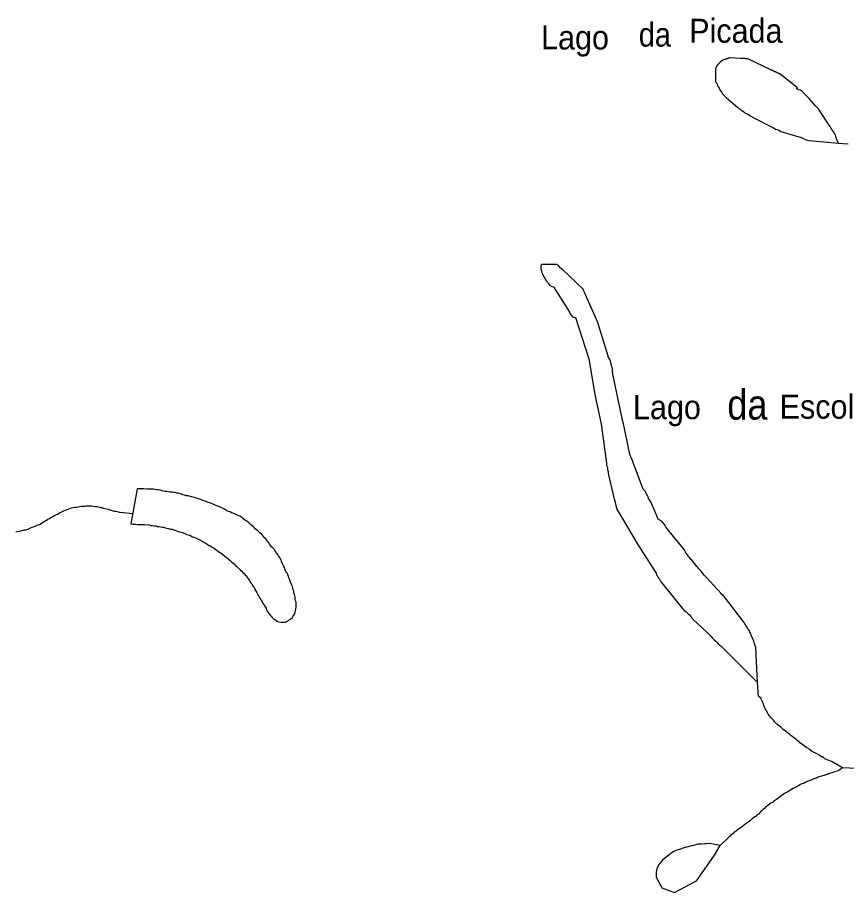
# Model space of a CAD drawing. Extents: x 785.9 to 812.4, y 7674.9 to 7703.1.
# Drawn here: x 788.66 to 791.421, y 7679.621 to 7682.535 of the extents above; entities that cross this region are included whole.
import ezdxf
from ezdxf.enums import TextEntityAlignment as Align

# ---------------------------------------------------------------- set-up
doc = ezdxf.new("R2010")
doc.units = 0
doc.header["$LTSCALE"] = 0.04
doc.linetypes.add('LONG_DASHED', pattern=[7.5, 6, -1.5])
for name, color, linetype, lineweight in [('2', 7, 'Continuous', 25), ('3', 7, 'LONG_DASHED', 25), ('7', 7, 'Continuous', 25)]:
    doc.layers.add(name, color=color, linetype=linetype, lineweight=lineweight)
doc.layers.add('61', color=7, linetype='Continuous')

msp = doc.modelspace()

# ---------------------------------------------------------------- linework, layer by layer
at = {"layer": '2'}
msp.add_line((789.058, 7680.9655), (789.0372, 7680.8488), dxfattribs=at)
for points in [[(789.5636, 7680.6691), (789.5619, 7680.6739), (789.5603, 7680.6796), (789.5579, 7680.6844), (789.5547, 7680.6885), (789.5522, 7680.6933), (789.5506, 7680.6982), (789.549, 7680.7039), (789.5458, 7680.7087), (789.5433, 7680.7136), (789.5417, 7680.7184), (789.5393, 7680.7233), (789.5377, 7680.7281), (789.5328, 7680.7379), (789.5296, 7680.7419), (789.5272, 7680.7468), (789.5239, 7680.7516), (789.5207, 7680.7557), (789.5174, 7680.7605), (789.5142, 7680.7646), (789.5102, 7680.7686), (789.5061, 7680.7726), (789.5029, 7680.7767), (789.4996, 7680.7815), (789.4964, 7680.7856), (789.4932, 7680.7896), (789.4899, 7680.7937), (789.4867, 7680.7985), (789.4827, 7680.8026), (789.4794, 7680.8066), (789.4754, 7680.8107), (789.4721, 7680.8147), (789.4681, 7680.818), (789.464, 7680.822), (789.46, 7680.826), (789.4519, 7680.8325), (789.4479, 7680.8366), (789.4446, 7680.8406), (789.4406, 7680.8438), (789.4357, 7680.8471), (789.4317, 7680.8511), (789.4276, 7680.8544), (789.4236, 7680.8576), (789.4187, 7680.86), (789.4147, 7680.8633), (789.4106, 7680.8665), (789.4066, 7680.8697), (789.4025, 7680.873), (789.3928, 7680.8778), (789.3872, 7680.8795), (789.3823, 7680.8819), (789.3775, 7680.8843), (789.3726, 7680.8859), (789.3678, 7680.8892), (789.3621, 7680.89), (789.3572, 7680.8924), (789.3475, 7680.8989), (789.3378, 7680.9037), (789.3233, 7680.9086), (789.3184, 7680.911), (789.3135, 7680.9134), (789.3087, 7680.9151), (789.3038, 7680.9175), (789.2893, 7680.9223), (789.2844, 7680.924), (789.2796, 7680.9256), (789.2747, 7680.928), (789.2698, 7680.9296), (789.265, 7680.9312), (789.2601, 7680.9329), (789.2545, 7680.9345), (789.2496, 7680.9361), (789.244, 7680.9377), (789.2391, 7680.9393), (789.2326, 7680.9409), (789.227, 7680.9426), (789.2213, 7680.9426), (789.2164, 7680.9442), (789.2108, 7680.9458), (789.2059, 7680.9474), (789.2011, 7680.949), (789.1962, 7680.9507), (789.1906, 7680.9515), (789.1849, 7680.9531), (789.1792, 7680.9531), (789.1736, 7680.9539), (789.1679, 7680.9539), (789.163, 7680.9555), (789.1574, 7680.9563), (789.1517, 7680.9571), (789.146, 7680.9579), (789.1363, 7680.9612), (789.1299, 7680.962), (789.1242, 7680.962), (789.1185, 7680.9636), (789.1129, 7680.9644), (789.0902, 7680.9644), (789.0805, 7680.9652), (789.0635, 7680.9652), (789.058, 7680.9655)], [(789.0372, 7680.8488), (789.0425, 7680.8479), (789.0538, 7680.8479), (789.0595, 7680.8471), (789.0708, 7680.8471), (789.0829, 7680.8463), (789.0983, 7680.8455), (789.104, 7680.8438), (789.1096, 7680.8438), (789.1145, 7680.8422), (789.1202, 7680.8422), (789.125, 7680.8406), (789.1307, 7680.8406), (789.1355, 7680.839), (789.1412, 7680.8382), (789.1469, 7680.8374), (789.1517, 7680.8358), (789.1574, 7680.8349), (789.163, 7680.8333), (789.1687, 7680.8317), (789.1744, 7680.8309), (789.1792, 7680.8293), (789.1849, 7680.8277), (789.1897, 7680.826), (789.1995, 7680.8228), (789.2043, 7680.8212)], [(789.2043, 7680.8212), (789.2092, 7680.8196), (789.214, 7680.818), (789.2189, 7680.8155), (789.2237, 7680.8139), (789.2286, 7680.8123), (789.2334, 7680.8107), (789.2431, 7680.8058), (789.248, 7680.8042), (789.2771, 7680.7896), (789.282, 7680.7864), (789.2868, 7680.7848), (789.2917, 7680.7815), (789.2965, 7680.7783), (789.3014, 7680.7759), (789.3063, 7680.7726), (789.3111, 7680.7702), (789.316, 7680.767), (789.3208, 7680.7637), (789.3249, 7680.7605), (789.3297, 7680.7573), (789.3338, 7680.754), (789.3386, 7680.7508), (789.3427, 7680.7476), (789.3508, 7680.7411), (789.3548, 7680.7379), (789.3589, 7680.7346), (789.3629, 7680.7314), (789.3669, 7680.7281), (789.3702, 7680.7241), (789.3742, 7680.7209), (789.3783, 7680.7176), (789.3823, 7680.7144), (789.3864, 7680.7103), (789.3904, 7680.7071), (789.4025, 7680.695), (789.4066, 7680.6909), (789.4106, 7680.6869), (789.4147, 7680.6836), (789.4179, 7680.6796), (789.422, 7680.6755), (789.4252, 7680.6707), (789.4284, 7680.6666), (789.4317, 7680.6618), (789.4341, 7680.6569), (789.4373, 7680.6529), (789.4406, 7680.6488), (789.443, 7680.644), (789.4454, 7680.6391), (789.4487, 7680.6351), (789.4503, 7680.6302), (789.4568, 7680.6205), (789.4592, 7680.6157), (789.4616, 7680.6108), (789.4649, 7680.606), (789.4673, 7680.6011), (789.4705, 7680.5971), (789.4729, 7680.5922), (789.4754, 7680.5873), (789.4786, 7680.5825), (789.481, 7680.5776), (789.4875, 7680.5679), (789.4891, 7680.5631), (789.4916, 7680.5582), (789.4948, 7680.5534), (789.5013, 7680.5453), (789.5045, 7680.5412), (789.5085, 7680.5372), (789.5126, 7680.5331), (789.5166, 7680.5299), (789.5215, 7680.5267), (789.5263, 7680.5242), (789.532, 7680.5226), (789.5377, 7680.5218), (789.5433, 7680.521), (789.5522, 7680.5218), (789.5619, 7680.5267), (789.566, 7680.5299), (789.57, 7680.5331), (789.5741, 7680.5364), (789.5773, 7680.5404), (789.5806, 7680.5445), (789.583, 7680.5493), (789.5854, 7680.5606), (789.587, 7680.5655), (789.5878, 7680.5712), (789.5878, 7680.5882), (789.5862, 7680.593), (789.5846, 7680.5987), (789.5846, 7680.6043), (789.5822, 7680.6141), (789.5806, 7680.6189), (789.5797, 7680.6246), (789.5781, 7680.6294), (789.5773, 7680.6351), (789.5757, 7680.6399), (789.5733, 7680.6448), (789.5708, 7680.6497), (789.5692, 7680.6545), (789.566, 7680.6642), (789.5636, 7680.6691)]]:
    msp.add_lwpolyline(points, dxfattribs=at)
at = {"layer": '3'}
for points in [[(791.0734, 7682.3987), (791.0718, 7682.3988), (791.0702, 7682.3989), (791.0686, 7682.399), (791.0686, 7682.399), (791.0332, 7682.4012), (791.0328, 7682.4011), (791.0312, 7682.4006), (791.0297, 7682.4001), (791.0282, 7682.3996), (791.0266, 7682.3991), (791.0251, 7682.3986), (791.0236, 7682.398), (791.022, 7682.3975), (791.0205, 7682.397), (791.019, 7682.3965), (791.0174, 7682.396), (791.0159, 7682.3955), (791.0144, 7682.395), (791.0095, 7682.3934), (791.0047, 7682.3901), (791.0006, 7682.3869), (790.9966, 7682.3828), (790.9925, 7682.3788), (790.9893, 7682.3747), (790.9868, 7682.3699), (790.9844, 7682.365), (790.9847, 7682.3222), (790.9849, 7682.3219), (790.9858, 7682.3205), (790.9867, 7682.3192), (790.9876, 7682.3178), (790.9885, 7682.3165), (790.9901, 7682.3141), (790.9917, 7682.3092), (790.9941, 7682.3044), (790.9966, 7682.2995), (790.999, 7682.2946), (791.0022, 7682.2898), (791.0055, 7682.2849), (791.0087, 7682.2809), (791.0127, 7682.2768), (791.02, 7682.2687), (791.0587, 7682.2353), (791.0591, 7682.235), (791.0604, 7682.2341), (791.0617, 7682.2332), (791.063, 7682.2322), (791.0644, 7682.2313), (791.0657, 7682.2304), (791.067, 7682.2295), (791.0683, 7682.2285), (791.0697, 7682.2276), (791.071, 7682.2267), (791.0791, 7682.221), (791.0831, 7682.2178), (791.088, 7682.2153), (791.0928, 7682.2129), (791.0977, 7682.2097), (791.1026, 7682.2064), (791.1123, 7682.2008), (791.1754, 7682.1684), (791.1754, 7682.1684), (791.1802, 7682.1668), (791.1851, 7682.1636), (791.1908, 7682.1619), (791.198, 7682.1587), (791.2029, 7682.1555), (791.2628, 7682.1377), (791.2676, 7682.1361), (791.2725, 7682.1344), (791.2773, 7682.132), (791.2822, 7682.1296), (791.287, 7682.128), (791.2927, 7682.1271), (791.2976, 7682.1255), (791.3089, 7682.1239), (791.3946, 7682.1167), (791.3939, 7682.1182), (791.3932, 7682.1196), (791.3924, 7682.1211), (791.3917, 7682.1225), (791.391, 7682.124), (791.3903, 7682.1254), (791.3895, 7682.1269), (791.3888, 7682.1283), (791.3881, 7682.1297), (791.3874, 7682.1312), (791.3866, 7682.1328), (791.3858, 7682.1393), (791.3841, 7682.1441), (791.3809, 7682.1482), (791.3785, 7682.153), (791.376, 7682.1579), (791.3728, 7682.1619), (791.3704, 7682.1668), (791.3671, 7682.1717), (791.3639, 7682.1765), (791.3607, 7682.1814), (791.355, 7682.1903), (791.3305, 7682.2281)], [(791.2582, 7682.3014), (791.2582, 7682.3014), (791.2004, 7682.3464), (791.199, 7682.3471), (791.1975, 7682.3478), (791.196, 7682.3485), (791.1946, 7682.3492), (791.1931, 7682.3499), (791.1916, 7682.3506), (791.1902, 7682.3513), (791.1887, 7682.352), (791.1873, 7682.3527), (791.1858, 7682.3534), (791.1843, 7682.3541), (791.1829, 7682.3547), (791.1814, 7682.3554), (791.1799, 7682.3561), (791.1785, 7682.3568), (791.177, 7682.3575), (791.1756, 7682.3582), (791.1741, 7682.3589), (791.1726, 7682.3596), (791.1712, 7682.3603), (791.1697, 7682.361), (791.1697, 7682.361), (791.0928, 7682.3975), (791.0912, 7682.3976), (791.0896, 7682.3977), (791.088, 7682.3978), (791.0863, 7682.3979), (791.0847, 7682.398), (791.0831, 7682.3981), (791.0815, 7682.3982), (791.0799, 7682.3983), (791.0783, 7682.3984), (791.0766, 7682.3985), (791.075, 7682.3986), (791.0734, 7682.3987)], [(791.3305, 7682.2281), (791.3303, 7682.2284), (791.3194, 7682.2404), (791.2959, 7682.2663), (791.2927, 7682.2704), (791.2887, 7682.2736), (791.2846, 7682.2777), (791.2806, 7682.2817), (791.2765, 7682.2857), (791.2725, 7682.2898), (791.2676, 7682.293), (791.2628, 7682.2946), (791.2547, 7682.2971), (791.2579, 7682.3011), (791.2582, 7682.3014)], [(790.8814, 7680.7619), (790.8291, 7680.826), (790.8226, 7680.8349), (790.8194, 7680.839), (790.8169, 7680.8438), (790.8137, 7680.8479), (790.8105, 7680.8527), (790.8072, 7680.8568), (790.7975, 7680.8625), (790.7959, 7680.8625), (790.7955, 7680.8625), (790.7708, 7680.9199), (790.7651, 7680.9288), (790.7619, 7680.9337), (790.7603, 7680.9385), (790.7579, 7680.9434), (790.7554, 7680.9482), (790.753, 7680.9531), (790.7506, 7680.9579), (790.7482, 7680.9604), (790.747, 7680.9615), (790.7459, 7680.9627), (790.7447, 7680.9638), (790.7441, 7680.9644), (790.7045, 7681.068), (790.7045, 7681.068), (790.7039, 7681.0695), (790.7033, 7681.071), (790.7027, 7681.0725), (790.7021, 7681.074), (790.7016, 7681.0755), (790.701, 7681.077), (790.7004, 7681.0786), (790.6998, 7681.0801), (790.6995, 7681.0808), (790.6769, 7681.1877), (790.6745, 7681.1926), (790.6737, 7681.1991), (790.6737, 7681.1995), (790.643, 7681.3479), (790.6422, 7681.3593), (790.6413, 7681.3649), (790.6405, 7681.3706), (790.6381, 7681.3755), (790.6373, 7681.3811), (790.6357, 7681.386), (790.6349, 7681.3916), (790.6324, 7681.3965), (790.6268, 7681.4054), (790.6268, 7681.407), (790.6268, 7681.4074), (790.596, 7681.5082), (790.5928, 7681.5195), (790.5904, 7681.5243), (790.5896, 7681.5258), (790.5889, 7681.5272), (790.5882, 7681.5287), (790.588, 7681.529), (790.5572, 7681.5996), (790.5572, 7681.5996), (790.5565, 7681.6011), (790.5559, 7681.6026), (790.5553, 7681.604), (790.5546, 7681.6055), (790.554, 7681.607), (790.5533, 7681.6085), (790.5527, 7681.61), (790.552, 7681.6115), (790.5514, 7681.6129), (790.5507, 7681.6144), (790.5501, 7681.6159), (790.5494, 7681.6174), (790.5488, 7681.6189), (790.5481, 7681.6203), (790.5475, 7681.6218), (790.5468, 7681.6233), (790.5462, 7681.6248), (790.5455, 7681.6263), (790.5449, 7681.6278), (790.5442, 7681.6292), (790.5436, 7681.6307), (790.4739, 7681.6975), (790.469, 7681.7007), (790.465, 7681.7048), (790.4617, 7681.7088), (790.4552, 7681.7121), (790.4536, 7681.7121), (790.4532, 7681.7121), (790.4051, 7681.7129), (790.4035, 7681.708), (790.4035, 7681.6983), (790.4051, 7681.6918), (790.4059, 7681.6862), (790.4083, 7681.6813), (790.4107, 7681.6765), (790.4132, 7681.6716), (790.4164, 7681.6667), (790.4188, 7681.6619), (790.4221, 7681.657), (790.4261, 7681.653), (790.4285, 7681.6481)], [(790.4285, 7681.6481), (790.4318, 7681.6441), (790.4399, 7681.6392), (790.4447, 7681.6384), (790.4451, 7681.6384), (790.4925, 7681.5632), (790.4981, 7681.5535), (790.5006, 7681.5486), (790.5038, 7681.5438), (790.507, 7681.5389), (790.5119, 7681.5373), (790.5184, 7681.5365), (790.5188, 7681.5364), (790.5629, 7681.3981), (790.5831, 7681.2792), (790.5831, 7681.2792), (790.6041, 7681.1805), (790.6041, 7681.1805), (790.6203, 7681.0599), (790.6219, 7681.0494), (790.6219, 7681.0437), (790.6235, 7681.0389), (790.6252, 7681.034), (790.6252, 7681.0283), (790.6268, 7681.0235), (790.6276, 7681.0178), (790.6284, 7681.0121), (790.6478, 7680.9312), (790.6478, 7680.9312), (790.6482, 7680.9297), (790.6486, 7680.9281), (790.649, 7680.9265), (790.6493, 7680.9249), (790.6497, 7680.9234), (790.6501, 7680.9218), (790.6505, 7680.9202), (790.6508, 7680.9186), (790.6512, 7680.9171), (790.6516, 7680.9155), (790.652, 7680.9139), (790.6523, 7680.9124), (790.6527, 7680.9108), (790.6531, 7680.9092), (790.6535, 7680.9076), (790.6539, 7680.9061), (790.6542, 7680.9045), (790.6546, 7680.9029), (790.655, 7680.9013), (790.6554, 7680.8998), (790.6557, 7680.8982), (790.7271, 7680.7783), (790.7271, 7680.7783), (790.787, 7680.6844), (790.787, 7680.682), (790.7878, 7680.6806), (790.7887, 7680.6793), (790.7896, 7680.6779), (790.7904, 7680.6765), (790.7913, 7680.6751), (790.7921, 7680.6738), (790.793, 7680.6724), (790.7938, 7680.671), (790.7947, 7680.6697), (790.7955, 7680.6683), (790.7964, 7680.6669), (790.7972, 7680.6655), (790.7981, 7680.6642), (790.799, 7680.6628), (790.7998, 7680.6614), (790.8007, 7680.66), (790.8015, 7680.6587), (790.8024, 7680.6573), (790.8032, 7680.6559), (790.8041, 7680.6545), (790.8049, 7680.6532), (790.8736, 7680.5679), (790.8776, 7680.5647), (790.8809, 7680.5606), (790.8857, 7680.5574), (790.8898, 7680.5534), (790.8938, 7680.5493), (790.8978, 7680.5461), (790.9019, 7680.542), (790.9035, 7680.5396), (790.9044, 7680.5383), (790.9053, 7680.5369), (790.9062, 7680.5356), (790.9071, 7680.5342), (790.9073, 7680.5339), (790.9585, 7680.4854), (790.9666, 7680.4773), (790.9699, 7680.4733), (790.9739, 7680.4692), (790.9779, 7680.4652), (790.982, 7680.4611), (790.986, 7680.4579), (790.9901, 7680.4538), (790.9941, 7680.4498), (791.0047, 7680.4401), (791.0058, 7680.439), (791.007, 7680.4379)], [(791.0038, 7680.6165), (791.0038, 7680.6165), (790.9553, 7680.6699), (790.9512, 7680.6739), (790.9472, 7680.678), (790.944, 7680.6828), (790.9399, 7680.6869), (790.9367, 7680.6909), (790.9334, 7680.695), (790.9294, 7680.699), (790.9262, 7680.7031), (790.9229, 7680.7071), (790.9148, 7680.7168), (790.9067, 7680.7265), (790.9027, 7680.7306), (790.8995, 7680.7354), (790.8954, 7680.7395), (790.8922, 7680.7443), (790.8881, 7680.7484), (790.8873, 7680.75), (790.8815, 7680.7616), (790.8814, 7680.7619)], [(791.007, 7680.4379), (791.0082, 7680.4368), (791.0094, 7680.4357), (791.0106, 7680.4346), (791.0118, 7680.4335), (791.0121, 7680.4332), (791.1163, 7680.3292), (791.1163, 7680.3292), (791.1175, 7680.3281), (791.1186, 7680.3269), (791.1197, 7680.3258), (791.1209, 7680.3247), (791.122, 7680.3235), (791.1232, 7680.3224), (791.1243, 7680.3212), (791.1249, 7680.3207), (791.1187, 7680.4368), (791.1171, 7680.4425), (791.1163, 7680.4482), (791.1139, 7680.453), (791.1123, 7680.4587), (791.1098, 7680.4636), (791.1082, 7680.4684), (791.1042, 7680.4781), (791.1026, 7680.483), (791.0993, 7680.4878), (791.0977, 7680.4927), (791.0945, 7680.4967), (791.0912, 7680.5008), (791.0888, 7680.5056), (791.0864, 7680.5097), (791.0855, 7680.5111), (791.0847, 7680.5124), (791.0839, 7680.5138), (791.083, 7680.5152), (791.0822, 7680.5166), (791.0814, 7680.518), (791.0805, 7680.5194), (791.0797, 7680.5208), (791.0795, 7680.5211), (791.0184, 7680.6019), (791.0103, 7680.61), (791.0063, 7680.6141), (791.0038, 7680.6165)], [(790.8345, 7679.7497), (790.8096, 7679.7305), (790.8024, 7679.7224), (790.7991, 7679.7183), (790.7959, 7679.7143), (790.7935, 7679.7094), (790.791, 7679.7046), (790.7894, 7679.6997), (790.7878, 7679.6949), (790.787, 7679.6892), (790.787, 7679.6843), (790.787, 7679.6827), (790.787, 7679.6811), (790.787, 7679.6795), (790.787, 7679.6779), (790.787, 7679.6763), (790.787, 7679.6746), (790.787, 7679.673), (790.787, 7679.6726), (790.804, 7679.6415), (790.804, 7679.6415), (790.8048, 7679.64), (790.8055, 7679.6386), (790.8063, 7679.6372), (790.8485, 7679.6212), (790.8485, 7679.6212), (790.9213, 7679.6601), (790.9245, 7679.6649), (790.982, 7679.7458), (790.982, 7679.7458), (791.0006, 7679.7782), (791.0006, 7679.7782), (790.9658, 7679.7839), (790.9545, 7679.7831), (790.9488, 7679.7831), (790.9375, 7679.7823), (790.9343, 7679.7823), (790.9326, 7679.7823), (790.931, 7679.7823), (790.9294, 7679.7823), (790.9278, 7679.7823), (790.9262, 7679.7823), (790.9258, 7679.7823), (790.912, 7679.7781), (790.912, 7679.7781)], [(790.912, 7679.7781), (790.9112, 7679.7779), (790.9003, 7679.775), (790.876, 7679.7685), (790.8711, 7679.7669), (790.8614, 7679.7636), (790.8558, 7679.762), (790.8509, 7679.7596), (790.8461, 7679.758), (790.8404, 7679.7539), (790.8351, 7679.7502), (790.8345, 7679.7497)]]:
    msp.add_lwpolyline(points, dxfattribs=at)
at = {"layer": '7'}
msp.add_line((789.0017, 7680.8875), (789.0433, 7680.883), dxfattribs=at)
for points in [[(791.3946, 7682.1167), (791.4266, 7682.1143)], [(788.6541, 7680.8228), (788.6598, 7680.8236), (788.6654, 7680.8244), (788.6711, 7680.8252), (788.6824, 7680.8285), (788.6881, 7680.8293), (788.6937, 7680.8309), (788.7034, 7680.8358), (788.7083, 7680.8374), (788.7132, 7680.839), (788.718, 7680.8414), (788.7229, 7680.843), (788.7277, 7680.8455), (788.7334, 7680.8471), (788.7382, 7680.8503), (788.7431, 7680.8536), (788.7479, 7680.856), (788.752, 7680.8592), (788.7568, 7680.8608), (788.7609, 7680.8641), (788.7658, 7680.8665), (788.7706, 7680.8697), (788.7755, 7680.8722), (788.7803, 7680.8754), (788.7852, 7680.8778), (788.79, 7680.8795), (788.7949, 7680.8819), (788.7997, 7680.8851), (788.8094, 7680.89), (788.8143, 7680.8924), (788.8192, 7680.8948), (788.824, 7680.8964), (788.8289, 7680.8981), (788.8345, 7680.8997), (788.8394, 7680.9021), (788.845, 7680.9029), (788.8507, 7680.9045), (788.8564, 7680.9045), (788.8669, 7680.907), (788.8726, 7680.9078), (788.8839, 7680.9078), (788.8887, 7680.9094), (788.9001, 7680.9094), (788.9057, 7680.9086), (788.9114, 7680.9078), (788.9187, 7680.907), (788.9243, 7680.9062), (788.93, 7680.9053), (788.9349, 7680.9037), (788.9405, 7680.9029), (788.9454, 7680.9013), (788.9502, 7680.8997), (788.9559, 7680.8989), (788.9616, 7680.8973), (788.9664, 7680.8956), (788.9721, 7680.8948), (788.9818, 7680.8916), (788.9875, 7680.8908), (788.9931, 7680.89), (788.998, 7680.8875), (789.0017, 7680.8875)], [(791.4076, 7680.0363), (791.3833, 7680.0509), (791.3785, 7680.0533), (791.3736, 7680.0566), (791.3688, 7680.0582), (791.3639, 7680.0606), (791.3591, 7680.0622), (791.3542, 7680.0646), (791.3493, 7680.0663), (791.3453, 7680.0695), (791.3404, 7680.0727), (791.3356, 7680.0744), (791.3315, 7680.0776), (791.3275, 7680.0808), (791.3226, 7680.0833), (791.3178, 7680.0849), (791.3065, 7680.0913), (791.2984, 7680.097), (791.2943, 7680.1002), (791.2895, 7680.1035), (791.2798, 7680.11), (791.2757, 7680.1132), (791.2709, 7680.1164), (791.266, 7680.1197), (791.262, 7680.1237), (791.2571, 7680.1269), (791.2531, 7680.131), (791.249, 7680.1342), (791.245, 7680.1375), (791.2401, 7680.1407), (791.2361, 7680.1439), (791.232, 7680.1472), (791.2239, 7680.1536), (791.2199, 7680.1577), (791.215, 7680.1609), (791.2102, 7680.1642), (791.2061, 7680.1682), (791.2021, 7680.1714), (791.198, 7680.1747), (791.194, 7680.1787), (791.1891, 7680.182), (791.1851, 7680.186), (791.181, 7680.1901), (791.1778, 7680.1949), (791.1738, 7680.199), (791.1705, 7680.203), (791.1673, 7680.2071), (791.1641, 7680.2111), (791.1608, 7680.2151), (791.1576, 7680.22), (791.156, 7680.2249), (791.1527, 7680.2289), (791.1503, 7680.2338), (791.1479, 7680.2386), (791.1463, 7680.2435), (791.1446, 7680.2483), (791.1422, 7680.2532), (791.1406, 7680.258), (791.1382, 7680.2629), (791.1365, 7680.2677), (791.1276, 7680.275), (791.1249, 7680.3207)], [(791.4076, 7680.0363), (791.3955, 7680.0274), (791.3906, 7680.0258), (791.3858, 7680.0242), (791.3809, 7680.0226), (791.376, 7680.0209), (791.3615, 7680.0161), (791.3566, 7680.0145), (791.3518, 7680.0129), (791.3469, 7680.0104), (791.3413, 7680.0096), (791.3267, 7680.0048), (791.3218, 7680.0023), (791.317, 7680.0007), (791.3073, 7679.9975), (791.3024, 7679.9951), (791.2976, 7679.9934), (791.2927, 7679.9918), (791.2879, 7679.9894), (791.283, 7679.9878), (791.2781, 7679.9845), (791.2725, 7679.9829), (791.2676, 7679.9805), (791.2628, 7679.9773), (791.2579, 7679.9756), (791.2531, 7679.9724), (791.2433, 7679.9675), (791.2385, 7679.9643), (791.2336, 7679.9611), (791.2288, 7679.9586), (791.2239, 7679.9554), (791.2142, 7679.9506), (791.2102, 7679.9473), (791.2053, 7679.9441), (791.2013, 7679.9408), (791.1964, 7679.9376), (791.1924, 7679.9344), (791.1883, 7679.9311), (791.1786, 7679.9247), (791.1746, 7679.9214), (791.1697, 7679.9182), (791.1649, 7679.915), (791.16, 7679.9117), (791.156, 7679.9085), (791.1519, 7679.9052), (791.1479, 7679.9012), (791.1438, 7679.8972), (791.1398, 7679.8939), (791.1357, 7679.8907), (791.1276, 7679.8826), (791.1236, 7679.8793), (791.1204, 7679.8753), (791.1155, 7679.8737), (791.1115, 7679.8696), (791.1066, 7679.8664), (791.1026, 7679.8624), (791.0985, 7679.8591), (791.0937, 7679.8559), (791.0896, 7679.8526), (791.0856, 7679.8494), (791.0815, 7679.8462), (791.0775, 7679.8429), (791.0734, 7679.8397), (791.0645, 7679.8348), (791.0572, 7679.8292), (791.0532, 7679.8259), (791.0483, 7679.8227), (791.0443, 7679.8187), (791.0403, 7679.8154), (791.0362, 7679.8122), (791.0322, 7679.8081), (791.0314, 7679.8073), (791.0256, 7679.8016), (791.0251, 7679.801), (791.0006, 7679.7782)], [(792.2204, 7679.9952), (792.1747, 7680.0025), (792.1251, 7680.0153), (792.0995, 7680.0186), (792.0772, 7680.0186), (792.0343, 7680.0164), (792.0037, 7680.0075), (791.9803, 7680.0008), (791.9284, 7679.9986), (791.8917, 7680.0047), (791.8621, 7680.013), (791.8398, 7680.0197), (791.7735, 7680.0314), (791.7022, 7680.0364), (791.6286, 7680.0387), (791.5439, 7680.0364), (791.4771, 7680.0325), (791.4076, 7680.0363)]]:
    msp.add_lwpolyline(points, dxfattribs=at)

# ---------------------------------------------------------------- texts
at = {"layer": '61'}
for s, width, p in [('Picada', 0.95, (790.8973, 7682.4509)), ('Lago', 0.95, (790.4038, 7682.4287)), ('da', 0.9, (790.7293, 7682.4382)), ('Escola', 0.95, (791.1985, 7681.1991)), ('Lago', 0.95, (790.71, 7681.1975))]:
    msp.add_text(s, height=0.08, dxfattribs=dict(at, width=width)).set_placement(p)
at = {"layer": '61', "width": 0.9}
msp.add_text('da', height=0.1, dxfattribs=at).set_placement((791.0911, 7681.1961), align=Align.CENTER)

doc.saveas('drawing.dxf')
